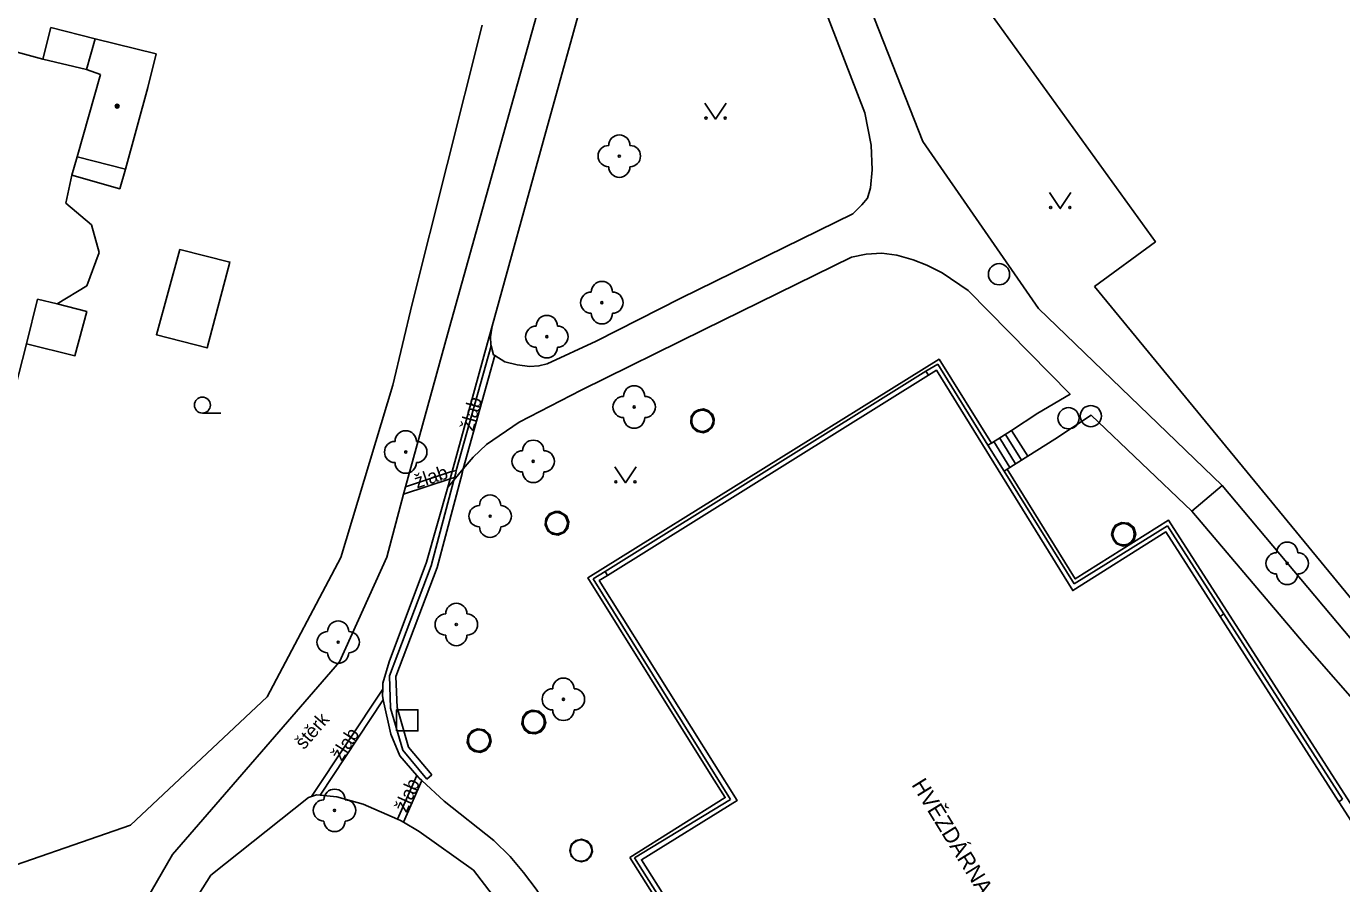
# Model space of a CAD drawing. Extents: x -600391 to -599491, y -1160176 to -1159402.
# Drawn here: x -599857 to -599795.1, y -1159492.9 to -1159452.6 of the extents above; entities that cross this region are included whole.
import ezdxf

# ---------------------------------------------------------------- set-up
doc = ezdxf.new("R2010")
doc.units = 0
for name, color, linetype in [('Level 10', 7, 'Continuous'), ('Level 11', 7, 'Continuous'), ('Level 22', 7, 'Continuous'), ('Level 26', 7, 'Continuous'), ('Level 27', 7, 'Continuous'), ('Level 36', 7, 'Continuous'), ('Level 39', 7, 'Continuous'), ('Level 40', 7, 'Continuous'), ('Level 41', 7, 'Continuous'), ('Level 42', 7, 'Continuous'), ('Level 5', 7, 'Continuous'), ('Level 7', 7, 'Continuous')]:
    doc.layers.add(name, color=color, linetype=linetype)

msp = doc.modelspace()

# ---------------------------------------------------------------- linework, layer by layer
at = {"layer": 'Level 10'}
msp.add_lwpolyline([(-599802.17, -1159475.39), (-599796.84, -1159481.68), (-599793.84, -1159485.09), (-599791.17, -1159488.1), (-599791.54, -1159488.45), (-599791.62, -1159488.72), (-599791.58, -1159488.97), (-599791.42, -1159489.18), (-599791.2, -1159489.29), (-599790.99, -1159489.31), (-599790.77, -1159489.22), (-599790.46, -1159488.89), (-599784.4, -1159495.87), (-599777.54, -1159504.59)], dxfattribs=at)
at = {"layer": 'Level 11'}
for points in [[(-599824.82, -1159429.8), (-599825.32, -1159431.32), (-599814.82, -1159457.98), (-599809.38, -1159465.84)], [(-599826.15, -1159434.38), (-599822.42, -1159444.02), (-599817.56, -1159456.63), (-599817.25, -1159458.16), (-599817.21, -1159459.31), (-599817.29, -1159460.17), (-599817.43, -1159460.65), (-599817.69, -1159460.97), (-599818.12, -1159461.39), (-599826.21, -1159465.35), (-599830.2, -1159467.38), (-599832.5, -1159468.45), (-599832.89, -1159468.55), (-599833.32, -1159468.57), (-599833.91, -1159468.5), (-599834.5, -1159468.36), (-599834.96, -1159468.06), (-599835.03, -1159468.02), (-599835.14, -1159467.6), (-599835.15, -1159467.56), (-599835.17, -1159467.18), (-599835.09, -1159466.67)], [(-599835.09, -1159466.67), (-599832.69, -1159457.99), (-599826.15, -1159434.38)], [(-599828.47, -1159435.81), (-599837.19, -1159467.07)], [(-599856.24, -1159454.11), (-599855.86, -1159452.62), (-599853.77, -1159453.15)], [(-599852.34, -1159459.29), (-599852.62, -1159460.21), (-599854.87, -1159459.57)], [(-599849.79, -1159463.06), (-599847.43, -1159463.66), (-599848.51, -1159467.7), (-599850.89, -1159467.08), (-599849.79, -1159463.06)], [(-599836.45, -1159473.39), (-599835.98, -1159472.84), (-599835.36, -1159472.24), (-599833.82, -1159471.19), (-599830.9, -1159469.69), (-599825.11, -1159466.84), (-599818.18, -1159463.42)], [(-599810.66, -1159471.59), (-599809.41, -1159470.77), (-599807.9, -1159469.88), (-599812.7, -1159465), (-599813.92, -1159464.17), (-599814.64, -1159463.81), (-599815.28, -1159463.55), (-599816.05, -1159463.33), (-599816.76, -1159463.24), (-599817.49, -1159463.28), (-599818.18, -1159463.42)], [(-599791.65, -1159483.17), (-599806.75, -1159464.81)], [(-599855.56, -1159465.62), (-599854.17, -1159465.99), (-599854.73, -1159468.07), (-599857, -1159467.51)], [(-599800.74, -1159474.18), (-599809.38, -1159465.84)], [(-599835.09, -1159466.67), (-599835.31, -1159467.46), (-599836.98, -1159473.51)], [(-599839.22, -1159474.41), (-599839.17, -1159474.24), (-599837.19, -1159467.07)], [(-599836.9, -1159473.92), (-599836.87, -1159473.8), (-599836.81, -1159473.59), (-599836.78, -1159473.47), (-599835.14, -1159467.6)], [(-599836.45, -1159473.39), (-599834.96, -1159468.06)], [(-599828.62, -1159491.69), (-599824.12, -1159488.87), (-599824.75, -1159487.87), (-599826.22, -1159485.53), (-599830.59, -1159478.52), (-599814.06, -1159468.23), (-599811.6, -1159472.18)], [(-599814.56, -1159468.98), (-599829.66, -1159478.41)], [(-599814.56, -1159468.98), (-599814.68, -1159468.79)], [(-599800.84, -1159480.34), (-599803.39, -1159476.36), (-599807.77, -1159479.12), (-599814.19, -1159468.75), (-599814.56, -1159468.98)], [(-599825.57, -1159470.71), (-599825.39, -1159470.61), (-599825.14, -1159470.57), (-599824.9, -1159470.66), (-599824.73, -1159470.82), (-599824.64, -1159471.05), (-599824.66, -1159471.28), (-599824.75, -1159471.46), (-599824.93, -1159471.62), (-599825.17, -1159471.69), (-599825.45, -1159471.63), (-599825.65, -1159471.46), (-599825.75, -1159471.23), (-599825.73, -1159470.93), (-599825.57, -1159470.71)], [(-599802.17, -1159475.39), (-599806.91, -1159470.87), (-599808.61, -1159472), (-599809.88, -1159472.8)], [(-599811.6, -1159472.18), (-599810.66, -1159471.59)], [(-599810.94, -1159471.77), (-599810.19, -1159472.99)], [(-599810.66, -1159471.59), (-599809.88, -1159472.8)], [(-599811.76, -1159472.28), (-599811.6, -1159472.18)], [(-599811.49, -1159472.11), (-599810.73, -1159473.33)], [(-599811.21, -1159471.94), (-599810.46, -1159473.16)], [(-599809.88, -1159472.8), (-599810.85, -1159473.41)], [(-599837.93, -1159487.8), (-599839.03, -1159486.49), (-599839.57, -1159484.62), (-599839.62, -1159483.17), (-599837.68, -1159478.03), (-599836.51, -1159473.61), (-599836.45, -1159473.39)], [(-599839.17, -1159474.24), (-599837.06, -1159473.53), (-599836.98, -1159473.51)], [(-599836.98, -1159473.51), (-599837.07, -1159473.86)], [(-599836.98, -1159473.51), (-599836.78, -1159473.47)], [(-599836.9, -1159473.92), (-599836.45, -1159473.39)], [(-599810.85, -1159473.41), (-599811, -1159473.5)], [(-599810.85, -1159473.41), (-599807.65, -1159478.57), (-599803.26, -1159475.81), (-599792.11, -1159493.18), (-599793.43, -1159494.03), (-599795.47, -1159495.3), (-599796.62, -1159496)], [(-599838.16, -1159488), (-599839.3, -1159486.63), (-599839.87, -1159484.66), (-599839.92, -1159483.13), (-599837.96, -1159477.95), (-599836.9, -1159473.92)], [(-599839.27, -1159474.58), (-599837.07, -1159473.86)], [(-599837.18, -1159474.25), (-599838.18, -1159477.78)], [(-599837.07, -1159473.86), (-599837.18, -1159474.25)], [(-599837.18, -1159474.25), (-599836.9, -1159473.92)], [(-599837.07, -1159473.86), (-599836.98, -1159473.83)], [(-599836.98, -1159473.83), (-599836.87, -1159473.8)], [(-599800.74, -1159474.18), (-599802.17, -1159475.39)], [(-599776.4, -1159503.18), (-599800.74, -1159474.18)], [(-599853.59, -1159501.32), (-599852.91, -1159496.37), (-599850.13, -1159491.55), (-599842.28, -1159482.47), (-599840.05, -1159477.55), (-599839.27, -1159474.58), (-599839.22, -1159474.41)], [(-599832.56, -1159475.74), (-599832.39, -1159475.51), (-599832.13, -1159475.4), (-599831.92, -1159475.4), (-599831.6, -1159475.6), (-599831.48, -1159475.88), (-599831.53, -1159476.19), (-599831.7, -1159476.39), (-599831.99, -1159476.51), (-599832.26, -1159476.46), (-599832.48, -1159476.31), (-599832.6, -1159476.03), (-599832.56, -1159475.74)], [(-599805.76, -1159476.05), (-599805.48, -1159475.91), (-599805.14, -1159475.95), (-599804.9, -1159476.15), (-599804.81, -1159476.45), (-599804.88, -1159476.73), (-599805.07, -1159476.94), (-599805.4, -1159477.03), (-599805.71, -1159476.92), (-599805.86, -1159476.74), (-599805.94, -1159476.49), (-599805.89, -1159476.24), (-599805.76, -1159476.05)], [(-599840.26, -1159484.06), (-599840.24, -1159483.76), (-599840.23, -1159483.48), (-599839.94, -1159482.48), (-599838.18, -1159477.78)], [(-599829.66, -1159478.41), (-599830.05, -1159478.65), (-599823.57, -1159489.01), (-599828.07, -1159491.79), (-599825.53, -1159495.81)], [(-599829.66, -1159478.41), (-599829.78, -1159478.22)], [(-599800.84, -1159480.34), (-599800.66, -1159480.22)], [(-599795.25, -1159489.06), (-599800.84, -1159480.34)], [(-599840.24, -1159483.76), (-599843.6, -1159488.82)], [(-599839.44, -1159486.9), (-599839.86, -1159485.88), (-599840.22, -1159484.26), (-599840.26, -1159484.06)], [(-599843.19, -1159488.76), (-599840.22, -1159484.26)], [(-599833.65, -1159485.08), (-599833.47, -1159484.85), (-599833.21, -1159484.75), (-599832.9, -1159484.8), (-599832.65, -1159485.02), (-599832.57, -1159485.33), (-599832.65, -1159485.59), (-599832.81, -1159485.77), (-599833.07, -1159485.87), (-599833.36, -1159485.83), (-599833.57, -1159485.68), (-599833.7, -1159485.39), (-599833.65, -1159485.08)], [(-599836.22, -1159485.95), (-599836.04, -1159485.73), (-599835.78, -1159485.63), (-599835.46, -1159485.67), (-599835.22, -1159485.89), (-599835.14, -1159486.2), (-599835.22, -1159486.46), (-599835.38, -1159486.64), (-599835.64, -1159486.74), (-599835.92, -1159486.7), (-599836.14, -1159486.55), (-599836.27, -1159486.27), (-599836.22, -1159485.95)], [(-599837.35, -1159489.03), (-599838.4, -1159488.06), (-599838.52, -1159487.95), (-599838.63, -1159487.82), (-599839.44, -1159486.9)], [(-599838.63, -1159487.82), (-599839.54, -1159489.89)], [(-599837.93, -1159487.8), (-599838.16, -1159488)], [(-599839.27, -1159490.03), (-599838.4, -1159488.06)], [(-599851.62, -1159501.27), (-599851.07, -1159496.86), (-599848.33, -1159492.52), (-599843.73, -1159488.87)], [(-599843.73, -1159488.87), (-599843.6, -1159488.82), (-599843.36, -1159488.74), (-599843.19, -1159488.76), (-599842.4, -1159488.83), (-599841.17, -1159489.17), (-599839.54, -1159489.89), (-599839.4, -1159489.95)], [(-599837.35, -1159489.03), (-599835.02, -1159490.89), (-599834.24, -1159491.64), (-599833.62, -1159492.39)], [(-599797.14, -1159495.85), (-599792.68, -1159493.06), (-599795.25, -1159489.06)], [(-599795.25, -1159489.06), (-599795.07, -1159488.94)], [(-599838.53, -1159490.47), (-599839.27, -1159490.03), (-599839.4, -1159489.95)], [(-599838.53, -1159490.47), (-599835.97, -1159492.29), (-599834.73, -1159493.9), (-599831.46, -1159500.52)], [(-599830.89, -1159490.82), (-599830.6, -1159490.92), (-599830.42, -1159491.13), (-599830.37, -1159491.4), (-599830.46, -1159491.65), (-599830.62, -1159491.81), (-599830.89, -1159491.89), (-599831.17, -1159491.82), (-599831.36, -1159491.64), (-599831.44, -1159491.36), (-599831.37, -1159491.08), (-599831.16, -1159490.88), (-599830.89, -1159490.82)], [(-599825.41, -1159496.75), (-599828.62, -1159491.69)], [(-599833.62, -1159492.39), (-599833.02, -1159493.18), (-599832.47, -1159494), (-599829.66, -1159500.15), (-599829.36, -1159500.24), (-599829.16, -1159500.48), (-599829.15, -1159500.76), (-599829.26, -1159501.01), (-599826.81, -1159506.35), (-599823.94, -1159512.72), (-599823.25, -1159514.28)]]:
    msp.add_lwpolyline(points, dxfattribs=at)
at = {"layer": 'Level 22'}
for centre in [(-599829.11, -1159458.67), (-599829.93, -1159465.57), (-599832.52, -1159467.17), (-599828.41, -1159470.48), (-599839.16, -1159472.6), (-599833.16, -1159473.04), (-599835.19, -1159475.62), (-599797.68, -1159477.84), (-599836.78, -1159480.72), (-599842.34, -1159481.55), (-599831.74, -1159484.24), (-599842.51, -1159489.47)]:
    msp.add_circle(centre, 0.05, dxfattribs=at)
for centre, start, end in [((-599829.61, -1159458.67), 90, 270), ((-599829.11, -1159458.17), 0, 180), ((-599828.61, -1159458.67), 270, 90), ((-599829.11, -1159459.17), 180, 0), ((-599829.93, -1159465.07), 0, 180), ((-599830.43, -1159465.57), 90, 270), ((-599829.43, -1159465.57), 270, 90), ((-599832.52, -1159466.67), 0, 180), ((-599829.93, -1159466.07), 180, 0), ((-599833.02, -1159467.17), 90, 270), ((-599832.02, -1159467.17), 270, 90), ((-599832.52, -1159467.67), 180, 0), ((-599828.41, -1159469.98), 0, 180), ((-599828.91, -1159470.48), 90, 270), ((-599827.91, -1159470.48), 270, 90), ((-599828.41, -1159470.98), 180, 0), ((-599839.16, -1159472.1), 0, 180), ((-599839.66, -1159472.6), 90, 270), ((-599838.66, -1159472.6), 270, 90), ((-599833.16, -1159472.54), 0, 180), ((-599833.66, -1159473.04), 90, 270), ((-599832.66, -1159473.04), 270, 90), ((-599839.16, -1159473.1), 180, 0), ((-599833.16, -1159473.54), 180, 0), ((-599835.19, -1159475.12), 0, 180), ((-599835.69, -1159475.62), 90, 270), ((-599834.69, -1159475.62), 270, 90), ((-599835.19, -1159476.12), 180, 0), ((-599798.18, -1159477.84), 90, 270), ((-599797.68, -1159477.34), 0, 180), ((-599797.18, -1159477.84), 270, 90), ((-599797.68, -1159478.34), 180, 0), ((-599836.78, -1159480.22), 0, 180), ((-599837.28, -1159480.72), 90, 270), ((-599836.28, -1159480.72), 270, 90), ((-599842.84, -1159481.55), 90, 270), ((-599842.34, -1159481.05), 0, 180), ((-599841.84, -1159481.55), 270, 90), ((-599836.78, -1159481.22), 180, 0), ((-599842.34, -1159482.05), 180, 0), ((-599831.74, -1159483.74), 0, 180), ((-599832.24, -1159484.24), 90, 270), ((-599831.24, -1159484.24), 270, 90), ((-599831.74, -1159484.74), 180, 0), ((-599842.51, -1159488.97), 0, 180), ((-599843.01, -1159489.47), 90, 270), ((-599842.01, -1159489.47), 270, 90), ((-599842.51, -1159489.97), 180, 0)]:
    msp.add_arc(centre, 0.5, start, end, dxfattribs=at)
at = {"layer": 'Level 26'}
msp.add_lwpolyline([(-599839.59, -1159485.73), (-599838.59, -1159485.73), (-599838.59, -1159484.73), (-599839.59, -1159484.73)], close=True, dxfattribs=at)
at = {"layer": 'Level 27'}
for centre in [(-599811.24, -1159464.23), (-599807.97, -1159471.01), (-599806.92, -1159470.91), (-599825.2, -1159471.13), (-599832.05, -1159475.95), (-599805.38, -1159476.47), (-599833.14, -1159485.31), (-599835.71, -1159486.18), (-599830.91, -1159491.36)]:
    msp.add_circle(centre, 0.5, dxfattribs=at)
at = {"layer": 'Level 36'}
msp.add_line((-599848.73, -1159470.765), (-599847.855, -1159470.765), dxfattribs=at)
for points in [[(-599825.08, -1159456.18), (-599824.58, -1159456.93), (-599824.08, -1159456.18)], [(-599808.86, -1159460.39), (-599808.36, -1159461.14), (-599807.86, -1159460.39)], [(-599829.32, -1159473.3), (-599828.82, -1159474.05), (-599828.32, -1159473.3)]]:
    msp.add_lwpolyline(points, dxfattribs=at)
for centre, radius in [((-599825.03, -1159456.88), 0.05), ((-599824.131, -1159456.88), 0.05), ((-599808.81, -1159461.09), 0.05), ((-599807.911, -1159461.09), 0.05), ((-599848.73, -1159470.39), 0.375), ((-599829.27, -1159474), 0.05), ((-599828.371, -1159474), 0.05)]:
    msp.add_circle(centre, radius, dxfattribs=at)
at = {"layer": 'Level 39'}
for radius in [0.09, 0.0398]:
    msp.add_circle((-599852.74, -1159456.32), radius, dxfattribs=at)
at = {"layer": 'Level 5'}
for points in [[(-599854.18, -1159454.6), (-599853.77, -1159453.15)], [(-599853.77, -1159453.15), (-599850.9, -1159453.85)], [(-599857.44, -1159453.77), (-599856.24, -1159454.11)], [(-599850.9, -1159453.85), (-599851.3, -1159455.44)], [(-599856.24, -1159454.11), (-599854.18, -1159454.6)], [(-599854.62, -1159458.7), (-599853.53, -1159454.83)], [(-599853.53, -1159454.83), (-599854.18, -1159454.6)], [(-599851.3, -1159455.44), (-599852.34, -1159459.29)], [(-599854.62, -1159458.7), (-599854.87, -1159459.57)], [(-599852.34, -1159459.29), (-599854.62, -1159458.7)], [(-599854.87, -1159459.57), (-599855.16, -1159460.88)], [(-599855.16, -1159460.88), (-599853.94, -1159461.91)], [(-599853.94, -1159461.91), (-599853.58, -1159463.2)], [(-599853.58, -1159463.2), (-599854.16, -1159464.78)], [(-599854.16, -1159464.78), (-599855.56, -1159465.62)], [(-599856.49, -1159465.4), (-599857, -1159467.51)], [(-599855.56, -1159465.62), (-599856.49, -1159465.4)], [(-599857, -1159467.51), (-599857.56, -1159469.65)], [(-599814.68, -1159468.79), (-599814.12, -1159468.47)], [(-599814.12, -1159468.47), (-599811.76, -1159472.28)], [(-599829.78, -1159478.22), (-599814.68, -1159468.79)], [(-599811.76, -1159472.28), (-599811, -1159473.5)], [(-599811, -1159473.5), (-599807.71, -1159478.8)], [(-599807.71, -1159478.8), (-599803.31, -1159476.07)], [(-599803.31, -1159476.07), (-599800.66, -1159480.22)], [(-599830.34, -1159478.57), (-599829.78, -1159478.22)], [(-599823.87, -1159488.95), (-599830.34, -1159478.57)], [(-599800.66, -1159480.22), (-599795.07, -1159488.94)], [(-599828.39, -1159491.7), (-599823.87, -1159488.95)], [(-599825.72, -1159495.93), (-599828.39, -1159491.7)]]:
    msp.add_lwpolyline(points, dxfattribs=at)
at = {"layer": 'Level 7'}
for points in [[(-599806.75, -1159464.81), (-599803.88, -1159462.7), (-599812.65, -1159450.54)], [(-599835.57, -1159452.5), (-599838.86, -1159465.63)], [(-599835.57, -1159452.5), (-599838.86, -1159465.63)], [(-599839.76, -1159469.46), (-599838.86, -1159465.63)], [(-599842.21, -1159477.57), (-599839.76, -1159469.46)], [(-599842.21, -1159477.57), (-599839.76, -1159469.46)], [(-599842.21, -1159477.57), (-599845.68, -1159484.12), (-599852.11, -1159490.17), (-599859.46, -1159492.71)]]:
    msp.add_lwpolyline(points, dxfattribs=at)

# ---------------------------------------------------------------- texts
at = {"layer": 'Level 40'}
msp.add_text('štěrk', height=0.65, rotation=49, dxfattribs=at).set_placement((-599843.95, -1159486.64))
at = {"layer": 'Level 41'}
msp.add_text('HVĚZDÁRNA MIKULÁŠE KOPERNÍKA', height=0.75, rotation=301.69, dxfattribs=at).set_placement((-599815.38, -1159488.26))
at = {"layer": 'Level 42'}
for rotation, p in [(74.56391, (-599835.99, -1159471.65)), (18.10493, (-599838.63, -1159474.32)), (57, (-599842.18, -1159487.19)), (66, (-599839.13, -1159489.61))]:
    msp.add_text('žlab', height=0.65, rotation=rotation, dxfattribs=at).set_placement(p)

doc.saveas('drawing.dxf')
